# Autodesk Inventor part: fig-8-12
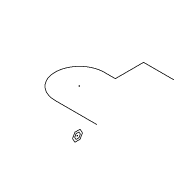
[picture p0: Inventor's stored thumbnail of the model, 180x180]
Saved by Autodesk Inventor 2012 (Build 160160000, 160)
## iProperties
Created: 2004-05
Part Number: fig-8-12
Document SubType Name: Modeling
Designer: CADCIM Technologies
Manufacturer: Standard
Standards Organization: Custom
Density: 1 g/cm^3
Material: Default
Author: CADCIM Technologies
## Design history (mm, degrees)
sketch "Sketch1"
  geometry: L1 (-42.583, 3.219)-(-90.066, 3.219); L2 (-90.066, 58.92)-(-77.282, 58.92); L3 (-77.282, 58.92)-(-77.282, 91.063); L4 (-77.282, 91.063)-(-42.583, 91.063); A1 r 27.851 centre (-90.066, 31.07) between (-90.066, 58.92) and (-90.066, 3.219)
  constraints: 8 end point, 2 parallel, 2 point on circle, 2 tangent, 1 centre point, 1 perpendicular
workplane "Work Plane2"
sketch "Sketch2"
  geometry: L1 (16.303, 0)-(19.151, 4.934); L2 (19.151, 4.934)-(24.849, 4.934); L3 (24.849, 4.934)-(27.697, 0); L4 (27.697, 0)-(24.849, -4.934); L5 (24.849, -4.934)-(19.151, -4.934); L6 (19.151, -4.934)-(16.303, 0); L7 (18.744, 0)-(20.372, 2.819); L8 (20.372, 2.819)-(23.628, 2.819); L9 (23.628, 2.819)-(25.256, 0); L10 (25.256, 0)-(23.628, -2.819); L11 (23.628, -2.819)-(20.372, -2.819); L12 (20.372, -2.819)-(18.744, 0); 2 further points
  constraints: 24 end point, 1 coincident, 22 other
